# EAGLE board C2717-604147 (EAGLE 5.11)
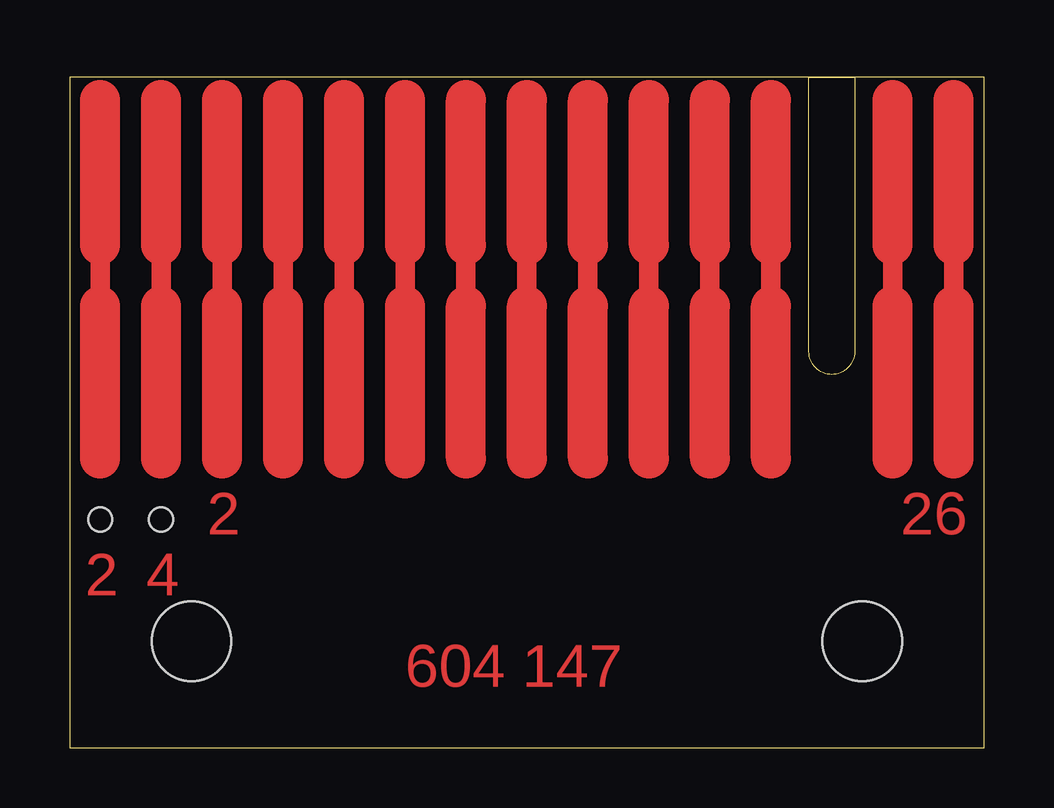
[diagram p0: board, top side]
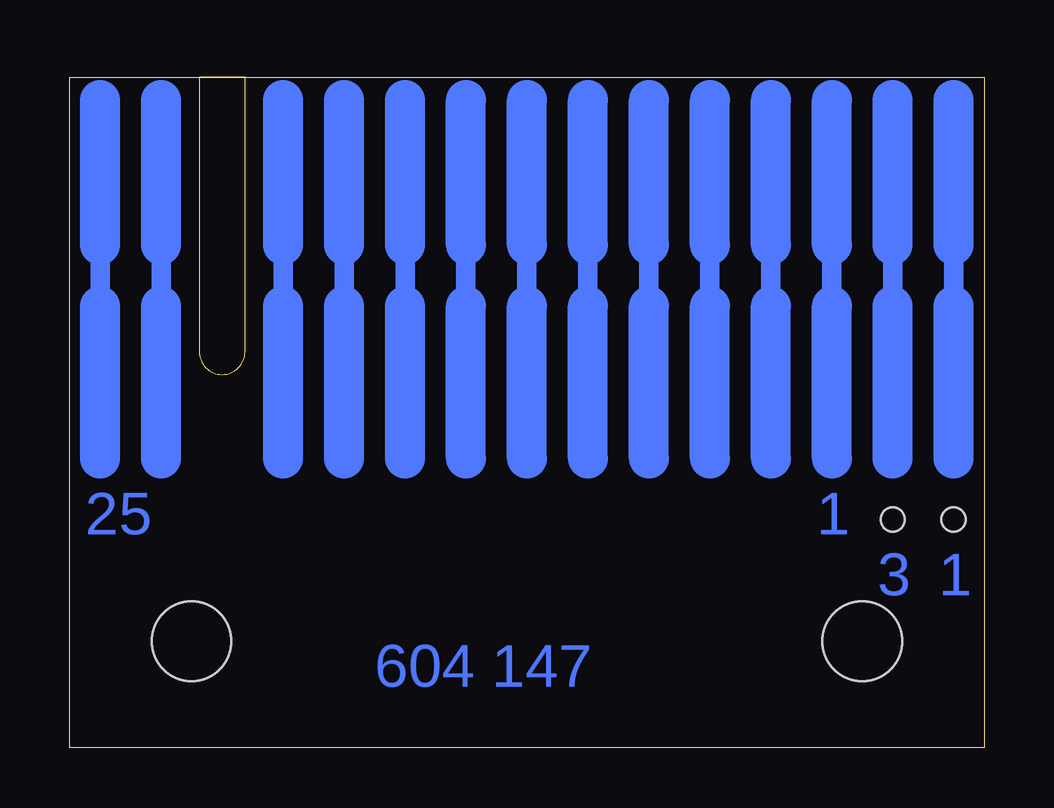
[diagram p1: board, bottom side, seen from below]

Size 38.1 x 27.94 mm. Coordinates in mm from the lower left corner, seen from the top.
Outline: 0,0 38.1,0 38.1,27.94 0,27.94 0,0
Copper layers (1*16): Top 0.0356mm / dielectric 1.5011mm / Bottom 0.0356mm
Design rules "LaenPCBOrder": minimum track width 6mil, minimum drill 13mil, track to track 6mil, track to pad 6mil, pad to pad 6mil, via to via 6mil, smd to smd 6mil, copper to edge 15mil, drill to drill 6mil, minimum pad ring 7mil, minimum via ring 7mil, stop-mask expansion 4mil, vias tented up to drill 0mil, thermal gap 10mil
Holes 3.3 mm at 5.08,4.45 33.02,4.45
Holes 1 mm at 1.27,9.53 3.81,9.53
Milling: 4 lines

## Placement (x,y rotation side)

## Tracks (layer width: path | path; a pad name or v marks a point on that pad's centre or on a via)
P1
  Bottom 0.813: 1.27,18.41 1.27,20.95
  Bottom 1.676: 1.27,20.95 1.27,26.99 | 1.27,12.06 1.27,18.41
P2
  Top 0.813: 1.27,18.41 1.27,20.95
  Top 1.676: 1.27,20.95 1.27,26.99 | 1.27,12.06 1.27,18.41
P3
  Bottom 0.813: 3.81,18.41 3.81,20.95
  Bottom 1.676: 3.81,20.95 3.81,26.99 | 3.81,12.06 3.81,18.41
P4
  Top 0.813: 3.81,18.41 3.81,20.95
  Top 1.676: 3.81,20.95 3.81,26.99 | 3.81,12.06 3.81,18.41
P5
  Bottom 0.813: 6.35,18.41 6.35,20.95
  Bottom 1.676: 6.35,20.95 6.35,26.99 | 6.35,12.06 6.35,18.41
P6
  Top 0.813: 6.35,18.41 6.35,20.95
  Top 1.676: 6.35,20.95 6.35,26.99 | 6.35,12.06 6.35,18.41
P7
  Bottom 0.813: 8.89,18.41 8.89,20.95
  Bottom 1.676: 8.89,20.95 8.89,26.99 | 8.89,12.06 8.89,18.41
P8
  Top 0.813: 8.89,18.41 8.89,20.95
  Top 1.676: 8.89,20.95 8.89,26.99 | 8.89,12.06 8.89,18.41
P9
  Bottom 0.813: 11.43,18.41 11.43,20.95
  Bottom 1.676: 11.43,20.95 11.43,26.99 | 11.43,12.06 11.43,18.41
P10
  Top 0.813: 11.43,18.41 11.43,20.95
  Top 1.676: 11.43,20.95 11.43,26.99 | 11.43,12.06 11.43,18.41
P11
  Bottom 0.813: 13.97,18.41 13.97,20.95
  Bottom 1.676: 13.97,20.95 13.97,26.99 | 13.97,12.06 13.97,18.41
P12
  Top 0.813: 13.97,18.41 13.97,20.95
  Top 1.676: 13.97,20.95 13.97,26.99 | 13.97,12.06 13.97,18.41
P13
  Bottom 0.813: 16.51,18.41 16.51,20.95
  Bottom 1.676: 16.51,20.95 16.51,26.99 | 16.51,12.06 16.51,18.41
P14
  Top 0.813: 16.51,18.41 16.51,20.95
  Top 1.676: 16.51,20.95 16.51,26.99 | 16.51,12.06 16.51,18.41
P15
  Bottom 0.813: 19.05,18.41 19.05,20.95
  Bottom 1.676: 19.05,20.95 19.05,26.99 | 19.05,12.06 19.05,18.41
P16
  Top 0.813: 19.05,18.41 19.05,20.95
  Top 1.676: 19.05,20.95 19.05,26.99 | 19.05,12.06 19.05,18.41
P17
  Bottom 0.813: 21.59,18.41 21.59,20.95
  Bottom 1.676: 21.59,20.95 21.59,26.99 | 21.59,12.06 21.59,18.41
P18
  Top 0.813: 21.59,18.41 21.59,20.95
  Top 1.676: 21.59,20.95 21.59,26.99 | 21.59,12.06 21.59,18.41
P19
  Bottom 0.813: 24.13,18.41 24.13,20.95
  Bottom 1.676: 24.13,20.95 24.13,26.99 | 24.13,12.06 24.13,18.41
P20
  Top 0.813: 24.13,18.41 24.13,20.95
  Top 1.676: 24.13,20.95 24.13,26.99 | 24.13,12.06 24.13,18.41
P21
  Top 0.813: 29.21,18.41 29.21,20.95
  Top 1.676: 29.21,20.95 29.21,26.99 | 29.21,12.06 29.21,18.41
P22
  Bottom 0.813: 29.21,18.41 29.21,20.95
  Bottom 1.676: 29.21,20.95 29.21,26.99 | 29.21,12.06 29.21,18.41
P23
  Bottom 0.813: 34.29,18.41 34.29,20.95
  Bottom 1.676: 34.29,20.95 34.29,26.99 | 34.29,12.06 34.29,18.41
P24
  Top 0.813: 34.29,18.41 34.29,20.95
  Top 1.676: 34.29,20.95 34.29,26.99 | 34.29,12.06 34.29,18.41
P25
  Bottom 0.813: 36.83,18.41 36.83,20.95
  Bottom 1.676: 36.83,20.95 36.83,26.99 | 36.83,12.06 36.83,18.41
P26
  Top 0.813: 36.83,18.41 36.83,20.95
  Top 1.676: 36.83,20.95 36.83,26.99 | 36.83,12.06 36.83,18.41
P27
  Bottom 0.813: 26.67,18.41 26.67,20.95
  Bottom 1.676: 26.67,20.95 26.67,26.99 | 26.67,12.06 26.67,18.41
P28
  Top 0.813: 26.67,18.41 26.67,20.95
  Top 1.676: 26.67,20.95 26.67,26.99 | 26.67,12.06 26.67,18.41

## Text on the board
Top: 2 | 26 | 2 | 4 | 604 147
Bottom: 1 | 25 | 1 | 3 | 604 147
